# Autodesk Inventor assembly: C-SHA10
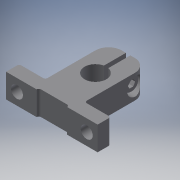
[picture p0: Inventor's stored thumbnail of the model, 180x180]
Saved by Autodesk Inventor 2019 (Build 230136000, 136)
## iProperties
Category: PARTsolutions
Company: MISUMI
Created: 2022-11
Part Number: C-SHA10
Catalog Web Link: www.cadenas.de
Description: C-SHA-Economy Shaft Supports - T-Shaped/Slit
Vendor: MISUMI
Document SubType Name: Assembly
Designer: psAdmin
Manufacturer: MISUMI
Mass: 6.70187 g
Surface Area: 40.5742 cm^2
Volume: 6.70187 cm^3
Density: 1 g/cm^3
Title: C-SHA10
Author: Cadenas PARTsolutions
Comments: Economy Shaft Supports - T-Shaped/Slit
PSOL_IDENT_0: {$CADENAS_DATA/23d-libs/misumi/metric/02_shaft_supports/c_sha_asmtab.prj},167 {VTYP=3D},{STYP=ASSTAB
PSOL_IDENT_1: },{NB=C-SHA10},{LINA=C-SHA10},{NN=C-SHA},{DATE=04.10.2022 06:54:20},{GEOMDATE=23.04.2021 02:50:35},{
PSOL_IDENT_2: VERSION=},{LINEID=10},{WBVAR=},{WBNUMERIC=}  {NB=C-SHA10},{LINA=C-SHA10},{KT=DUMMY},{PN=C-SHA10},{TY
PSOL_IDENT_3: PE=C-SHA},{D=10},{H=20},{H1=35},{T=11},{L1=32},{DD=5.5},{E=9.5},{S=6},{R=6},{L=42},{B=14},{W=18},{M=
PSOL_IDENT_4: M4},{R2=1},{W2=2.0},{M3D=4},{M3D2=6.0},{M3D3=8},{M3D4=4.3},{LB=10},{PPATH=c_sha/c_sha_asmtpl.prj}
NB: C-SHA10
NN: C-SHA
NT: Economy Shaft Supports - T-Shaped/Slit
NBSYN: $PN.
LINA: C-SHA10
CATALOG: Misumi
PN: C-SHA10
D: 10
H: 20
H1: 35
T: 11
L1: 32
DD: 5.5
E: 9.5
S: 6
R: 6
L: 42
B: 14
W: 18
M: M4
SUPPLIER: MISUMI
ARTICLENO: C-SHA10
BOMINFO: C-SHA10
CREATOR: CADENAS GmbH
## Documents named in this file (3)
- e:\temp\worker_COMMON_15\temp\tmp_4256_78_E3Duu\format_0\C-SHA10.iam
- e:\temp\worker_COMMON_15\temp\tmp_4256_78_E3Duu\format_0\C-SHA10_b.ipt
- e:\temp\worker_COMMON_15\temp\tmp_4256_78_E3Duu\format_0\BOLT4-10.ipt
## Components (2 placed, 2 different names)
1. C-SHA10_b:1 — to_bolt_XY@1 <-> to_cp_XY@2, to_bolt_Z@1 <-> to_cp_Z@2, to_bolt_YZ@1 <-> to_cp_YZ@2
2. BOLT4-10:1 — to_bolt_XY@1 <-> to_cp_XY@2, to_bolt_Z@1 <-> to_cp_Z@2, to_bolt_YZ@1 <-> to_cp_YZ@2
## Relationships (3: Mate 2, Angle 1)
- to_bolt_XY@1 <-> to_cp_XY@2 [Mate]: C-SHA10_b:1 ↔ BOLT4-10:1
- to_bolt_Z@1 <-> to_cp_Z@2 [Mate]: C-SHA10_b:1 ↔ BOLT4-10:1
- to_bolt_YZ@1 <-> to_cp_YZ@2 [Angle]: C-SHA10_b:1 ↔ BOLT4-10:1
